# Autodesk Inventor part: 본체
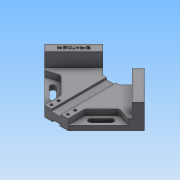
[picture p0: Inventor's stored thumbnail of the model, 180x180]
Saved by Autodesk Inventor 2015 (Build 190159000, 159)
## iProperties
Created: 2019-04
Part Number: 본체
Material: 알루미늄 6061
Document SubType Name: Modeling
Designer: SCD-A01
Density: 2.7 g/cm^3
Appearance: 기본값
Author: SCD-A01
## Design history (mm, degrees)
sketch "스케치3"
  geometry: L1 (84.853, 0)-(0, -84.853); L2 (0, -84.853)-(-84.853, 0); L3 (-84.853, 0)-(0, 84.853); L4 (0, 84.853)-(84.853, 0); L5 (42.426, -42.426)-(-42.426, 42.426); L6 (-60, -60)-(60, 60); 3 further points
  constraints: 12 end point, 4 midpoint, 3 parallel, 2 vertical alignment, 1 perpendicular
  dimensions: "d6" = 120 distance of L2.end L3.end; "d7" = 120 distance of L1.end L2.end; "d8" = 60 distance from line of point (0, 0) L4
extrude "돌출2" new body sketch "스케치3" distance "d9" = 18; taper "d10" = 0 deg
sketch "스케치4"
  geometry: L1 (0, -84.853)-(84.853, 0) reference; L2 (-84.853, 0)-(0, -84.853) reference; L3 (-40.47, -64.853)-(52.354, -64.853); L4 (-40.47, -64.853)-(-40.47, -87.492); L5 (-40.47, -87.492)-(52.354, -87.492); L6 (52.354, -87.492)-(52.354, -64.853); 1 further point
  constraints: 8 end point, 2 perpendicular, 1 horizontal, 1 vertical
  dimensions: "d11" = 20 distance from line of L1.start L3; "d12" = 92.82402 distance between parallel lines of L4 L6; "d13" = 22.63922 distance between parallel lines of L3 L5
extrude "돌출3" cut sketch "스케치4" distance "d14" = 18; taper "d15" = 0 deg
sketch "스케치6"
  geometry: L1 (84.853, 0)-(0, 84.853) reference; L2 (0, 84.853)-(-84.853, 0) reference; L3 (-84.853, 0)-(-20, -64.853) reference; L4 (-84.853, 0)-(-74.246, -10.607); L5 (-74.246, -10.607)-(10.607, 74.246); L6 (10.607, 74.246)-(0, 84.853); L7 (-84.853, 0)-(0, 84.853); 1 further point
  constraints: 8 end point, 2 point on line, 1 perpendicular
  dimensions: "d17" = 15 distance between parallel lines of L5 L2
extrude "돌출4" join sketch "스케치6" distance "d18" = 24; taper "d19" = 0 deg
sketch "스케치7"
  geometry: L1 (20, -64.853)-(84.853, 0) reference; L2 (84.853, 0)-(10.607, 74.246) reference; L3 (20, -64.853)-(-20, -64.853) reference; L4 (-20, -64.853)-(-74.246, -10.607) reference; L5 (10.607, 74.246)-(-74.246, -10.607) reference; L6 (0, 84.853)-(10.607, 74.246) reference; L7 (-84.853, 0)-(0, 84.853) reference; L8 (-74.246, -10.607)-(-84.853, 0) reference; L9 (84.853, 0)-(20, -64.853) reference; L10 (10.607, 74.246)-(84.853, 0) reference; L11 (84.853, 0)-(0, 84.853); L12 (0, 84.853)-(-10.607, 74.246); L13 (84.853, 0)-(74.246, -10.607); L14 (-10.607, 74.246)-(74.246, -10.607); 1 further point
  constraints: 8 end point, 2 collinear, 2 point on line, 1 perpendicular
  dimensions: "d21" = 15 distance between parallel lines of L2 L14
extrude "돌출5" join sketch "스케치7" distance "d22" = 24; taper "d23" = 0 deg
sketch "스케치8"
  geometry: L1 (0, 84.853)-(-84.853, 0) reference; L2 (0, 84.853)-(-35.355, 49.497); L3 (-35.355, 49.497)-(-14, 28.147); L4 (-14, 28.147)-(0, 28.147); L5 (0, 28.147)-(0, 84.853); L6 (-20, -64.853)-(20, -64.853) reference; 1 further point
  constraints: 8 end point, 1 horizontal, 1 perpendicular, 1 point on line
  dimensions: "d24" = 50 distance of L1.start L2.end; "d25" = 93 distance between parallel lines of L6 L4; "d27" = 14 distance of L3.end L4.end
extrude "돌출6" cut sketch "스케치8" stored distance "d28" = 24; taper "d29" = 0 deg
sketch "스케치9"
  geometry: L1 (40, -18)-(0, -18) reference; L2 (0, 0)-(40, 0) reference; L3 (12, 0)-(28, 0); L4 (28, 0)-(28, -3.5); L5 (28, -3.5)-(12, -3.5); L6 (12, -3.5)-(12, 0); 3 further points
  constraints: 8 end point, 2 midpoint, 2 parallel, 1 collinear, 1 horizontal, 1 perpendicular, 1 vertical alignment
  dimensions: "d30" = 16 distance of L4.end L5.end; "d31" = 3.5 distance of L3.end L4.end
extrude "돌출7" cut sketch "스케치9" stored distance "d32" = 24; taper "d33" = 0 deg
sketch "스케치10"
  geometry: L1 (40, 0)-(0, 0) reference; L2 (14, 3)-(26, 3); L3 (26, 3)-(26, 0); L4 (26, 0)-(14, 0); L5 (14, 0)-(14, 3); 2 further points
  constraints: 8 end point, 2 midpoint, 2 parallel, 1 collinear, 1 horizontal, 1 perpendicular
  dimensions: "d34" = 12 distance of L3.end L4.end; "d35" = 3 distance of L2.end L3.end
extrude "돌출8" cut sketch "스케치10" stored distance "d36" = 24; taper "d37" = 0 deg
sketch "스케치12"
  geometry: L1 (-8, -64.853)-(-8, 28.147) reference; L2 (-35.355, 49.497)-(-84.853, 0) reference; L3 (0, 0)-(0, -91.058); L4 (-70.711, -14.142)-(-49.497, -7.071); L5 (-49.497, -7.071)-(-20, -36.569); L6 (-20, -36.569)-(-20, -64.853); L7 (-20, -64.853)-(-70.711, -14.142); L8 (-74.246, -10.607)-(-20, -64.853) reference
  constraints: 10 end point, 2 parallel, 1 collinear, 1 vertical
  dimensions: "d43" = 20 distance from line of L8 L4.end; "d44" = 20 distance from line of L2 L4.start; "d45" = 20 distance from line of L3 L6.end; "d46" = 30 distance from line of L2 L4.end
extrude "돌출9" cut sketch "스케치12" distance "d47" = 10; taper "d48" = 0 deg
sketch "스케치15"
  geometry: L1 (-20, -64.853)-(-70.711, -14.142) reference; L2 (-49.497, -21.213)-(-32.527, -38.184); L3 (-52.679, -24.395)-(-35.709, -41.366); L4 (-29.345, -35.002)-(-46.315, -18.031); L5 (-49.497, -21.213)-(-25.497, -21.213); L6 (-35.355, 49.497)-(-84.853, 0) reference; A1 r 4.5 centre (-49.497, -21.213) between (-46.315, -18.031) and (-52.679, -24.395); A2 r 4.5 centre (-32.527, -38.184) between (-35.709, -41.366) and (-29.345, -35.002); 2 further points
  constraints: 10 end point, 4 point on circle, 4 tangent, 2 centre point, 1 equal length, 1 horizontal, 1 midpoint, 1 parallel
  dimensions: "d56" = 24 distance of L2.start L2.end; "d57" = 45 deg angle of L2 L5; "d58" = 9 diameter of A2; "d59" = 40 distance from line of L6 L2.start; "d60" = 10 distance from line of L1 L2.start
extrude "돌출10" cut sketch "스케치15" stored distance "d61" = 10; taper "d62" = 0 deg
sketch "스케치17"
  geometry: L1 (6, -64.853)-(20, -64.853) reference; L2 (0, 0)-(0, -60.396); 1 further point
  constraints: 2 end point, 1 vertical
  dimensions: "d64" = 6 distance from line of point (14, -58.853) L1; "d65" = 14 distance from line of L2 point (14, -58.853)
hole "구멍1" sketch "스케치17" at (14, -58.853) diameter "d66" = 4.5; stored, may be unused: countersink angle "d70" = 90 deg, drill point angle "d72" = 118 deg; dims "d67" = 6, "d68" = 8, "d69" = 10, "d71" = 8
fillet "모깎기1" dims "d76" = 5
fillet "모깎기2" dims "d77" = 5
sketch "스케치19"
  geometry: L1 (-24.747, 38.892)-(-35.355, 49.497) reference; L2 (-35.355, 49.497)-(-84.853, 0) reference; 2 further points
  constraints: 1 other
  dimensions: "d78" = 7.5 distance from line of L2 point (-54.8, 19.446); "d79" = 35 distance from line of L1 point (-54.8, 19.446)
feature "엠보싱1" sketch "스케치19" dims "d80" = 0.5, "d81" = 0
node "솔리드2"
mirror "대칭1"
mirror "대칭2"
mirror "대칭3"
pattern_linear "직사각형 패턴1" dims "d75" = 12
mirror "대칭4"
node "절단 모서리 투영1"
